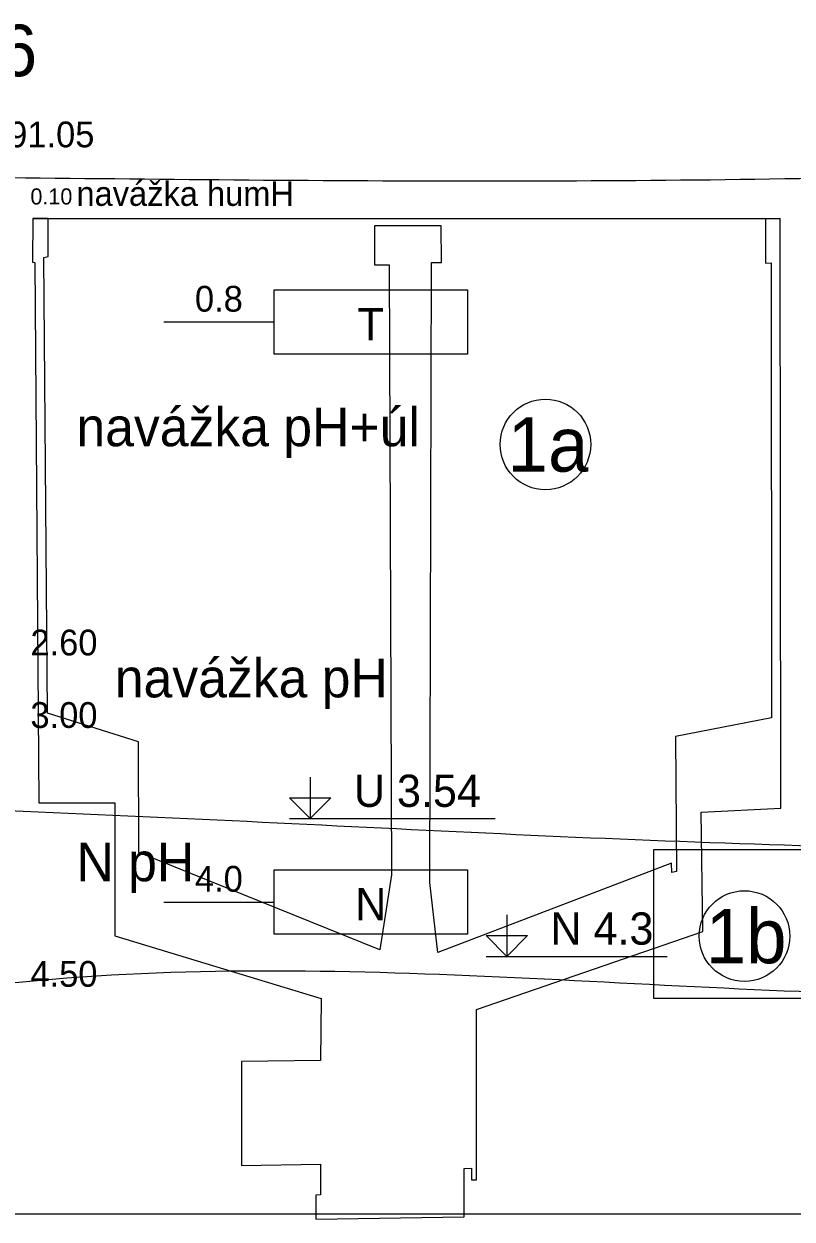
# Model space of a CAD drawing. Extents: x 3042 to 4120, y 576 to 2694.
# Drawn here: x 3392.8 to 3414, y 1987.44 to 2020.41 of the extents above; entities that cross this region are included whole.
import ezdxf

# ---------------------------------------------------------------- set-up
doc = ezdxf.new("R2010")
doc.units = 0
for name, color, linetype in [('16', 7, 'Continuous'), ('17', 7, 'Continuous'), ('52', 7, 'Continuous'), ('61', 7, 'Continuous'), ('62', 7, 'Continuous'), ('HPV', 7, 'Continuous'), ('komunikace', 7, 'Continuous'), ('nádrže', 7, 'Continuous'), ('rozhraní', 7, 'Continuous')]:
    doc.layers.add(name, color=color, linetype=linetype)

msp = doc.modelspace()

# ---------------------------------------------------------------- linework, layer by layer
at = {"layer": '61'}
for p, q in [((3400.128, 1998.483), (3405.801, 1998.483)), ((3405.552, 1994.683), (3410.547, 1994.683))]:
    msp.add_line(p, q, dxfattribs=at)
for points in [[(3400.7, 1999.626), (3400.7, 1998.483), (3400.128, 1999.055), (3401.271, 1999.055), (3400.7, 1998.483)], [(3406.123, 1995.826), (3406.123, 1994.683), (3405.552, 1995.255), (3406.695, 1995.255), (3406.123, 1994.683)]]:
    msp.add_lwpolyline(points, dxfattribs=at)
at = {"layer": '62'}
for p, q in [((3396.662, 2012.183), (3399.71, 2012.183)), ((3396.662, 1996.183), (3399.71, 1996.183))]:
    msp.add_line(p, q, dxfattribs=at)
for points in [[(3405.044, 2011.294), (3399.71, 2011.294), (3399.71, 2013.072), (3405.044, 2013.072), (3405.044, 2011.294)], [(3405.044, 1995.294), (3399.71, 1995.294), (3399.71, 1997.072), (3405.044, 1997.072), (3405.044, 1995.294)]]:
    msp.add_lwpolyline(points, dxfattribs=at)
at = {"layer": 'HPV'}
msp.add_spline([(3240.524, 2002.483), (3248.732, 2002.483), (3335.452, 1999.034), (3390.312, 1998.782), (3416.672, 1997.683), (3427.31, 1997.599)], degree=3, dxfattribs=at)
at = {"layer": 'komunikace'}
msp.add_line((3430.025, 1987.57), (3299.437, 1987.57), dxfattribs=at)
at = {"layer": 'nádrže'}
msp.add_line((3393.046, 2015.041), (3413.666, 2015.041), dxfattribs=at)
msp.add_lwpolyline([(3393.101, 2013.822), (3393.207, 1998.92), (3395.306, 1998.92), (3395.306, 1995.248), (3401.003, 1993.521), (3400.982, 1991.812), (3398.806, 1991.779), (3398.808, 1988.916), (3400.984, 1988.949), (3400.985, 1988.101), (3400.852, 1988.099), (3400.852, 1987.436), (3404.946, 1987.499), (3404.946, 1988.836), (3405.156, 1988.839), (3405.156, 1988.519), (3405.29, 1988.522), (3405.287, 1993.216), (3411.538, 1995.372), (3411.493, 1998.657), (3413.684, 1998.77), (3413.666, 2015.041), (3413.266, 2015.031), (3413.267, 2013.808), (3413.421, 2013.813), (3413.435, 2001.261), (3410.779, 2000.744), (3410.808, 1997.027), (3410.676, 1997.001), (3410.674, 1997.258), (3404.224, 1994.794), (3404.006, 1996.723), (3404.05, 2013.821), (3404.321, 2013.821), (3404.317, 2014.835), (3402.473, 2014.835), (3402.476, 2013.76), (3402.882, 2013.76), (3402.941, 1996.93), (3402.622, 1994.861), (3395.97, 1997.547), (3395.96, 2000.605), (3393.449, 2001.396), (3393.347, 2013.96), (3393.471, 2013.986), (3393.466, 2015.041), (3393.046, 2015.041), (3393.036, 2013.836), (3393.101, 2013.822)], dxfattribs=at)
at = {"layer": 'rozhraní'}
msp.add_lwpolyline([(3424.739, 1993.52), (3410.182, 1993.52), (3410.182, 1997.633), (3424.739, 1997.633)], close=True, dxfattribs=at)
for centre in [(3407.191, 2008.805), (3412.684, 1995.243)]:
    msp.add_circle(centre, 1.25, dxfattribs=at)
for points in [[(3429.536, 2016.622), (3416.672, 2016.183), (3390.375, 2016.183), (3366.013, 2016.433), (3335.107, 2016.483), (3314.994, 2016.483)], [(3240.289, 1991.983), (3248.732, 1991.983), (3335.452, 1992.983), (3365.632, 1988.433), (3390.312, 1993.683), (3416.672, 1993.64), (3427.306, 1993.683)]]:
    msp.add_spline(points, degree=3, dxfattribs=at)

# ---------------------------------------------------------------- texts
at = {"layer": '16'}
msp.add_text('HV226', height=1.4224, dxfattribs=at).set_placement((3387.348, 2018.962))
at = {"layer": '17'}
msp.add_text('191.05', height=0.7112, dxfattribs=at).set_placement((3391.836, 2017.001))
at = {"layer": '52'}
for s, height, p in [('navážka humH', 0.6731, (3394.249, 2015.386)), ('0.10', 0.4445, (3392.979, 2015.424)), ('navážka pH+úl', 1.0668, (3394.249, 2008.755)), ('2.60', 0.7112, (3392.979, 2002.985)), ('navážka pH', 1.0668, (3395.308, 2001.828)), ('3.00', 0.7112, (3392.979, 2000.985)), ('N pH', 1.0668, (3394.249, 1996.755)), ('4.50', 0.7112, (3392.979, 1993.844))]:
    msp.add_text(s, height=height, dxfattribs=at).set_placement(p)
at = {"layer": '61'}
for s, p in [('U 3.54', (3401.906, 1998.807)), ('N 4.3', (3407.33, 1995.007))]:
    msp.add_text(s, height=0.889, dxfattribs=at).set_placement(p)
at = {"layer": '62'}
for s, height, p in [('0.8', 0.7112, (3397.519, 2012.468)), ('T', 0.889, (3402.006, 2011.681)), ('4.0', 0.7112, (3397.519, 1996.468)), ('N', 0.889, (3401.943, 1995.681))]:
    msp.add_text(s, height=height, dxfattribs=at).set_placement(p)
at = {"layer": 'rozhraní'}
for s, p in [('1a', (3406.148, 2008.055)), ('1b', (3411.615, 1994.493))]:
    msp.add_text(s, height=1.5, dxfattribs=at).set_placement(p)

doc.saveas('drawing.dxf')
